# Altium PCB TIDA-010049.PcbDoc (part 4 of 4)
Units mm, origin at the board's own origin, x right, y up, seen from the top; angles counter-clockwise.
Board outline 75 x 60 mm, 4 copper layers (Top Layer, GND, Supply, Bottom Layer), stack 1.565 mm thick; 309 components, 186 nets, 995 pads, 362 vias.
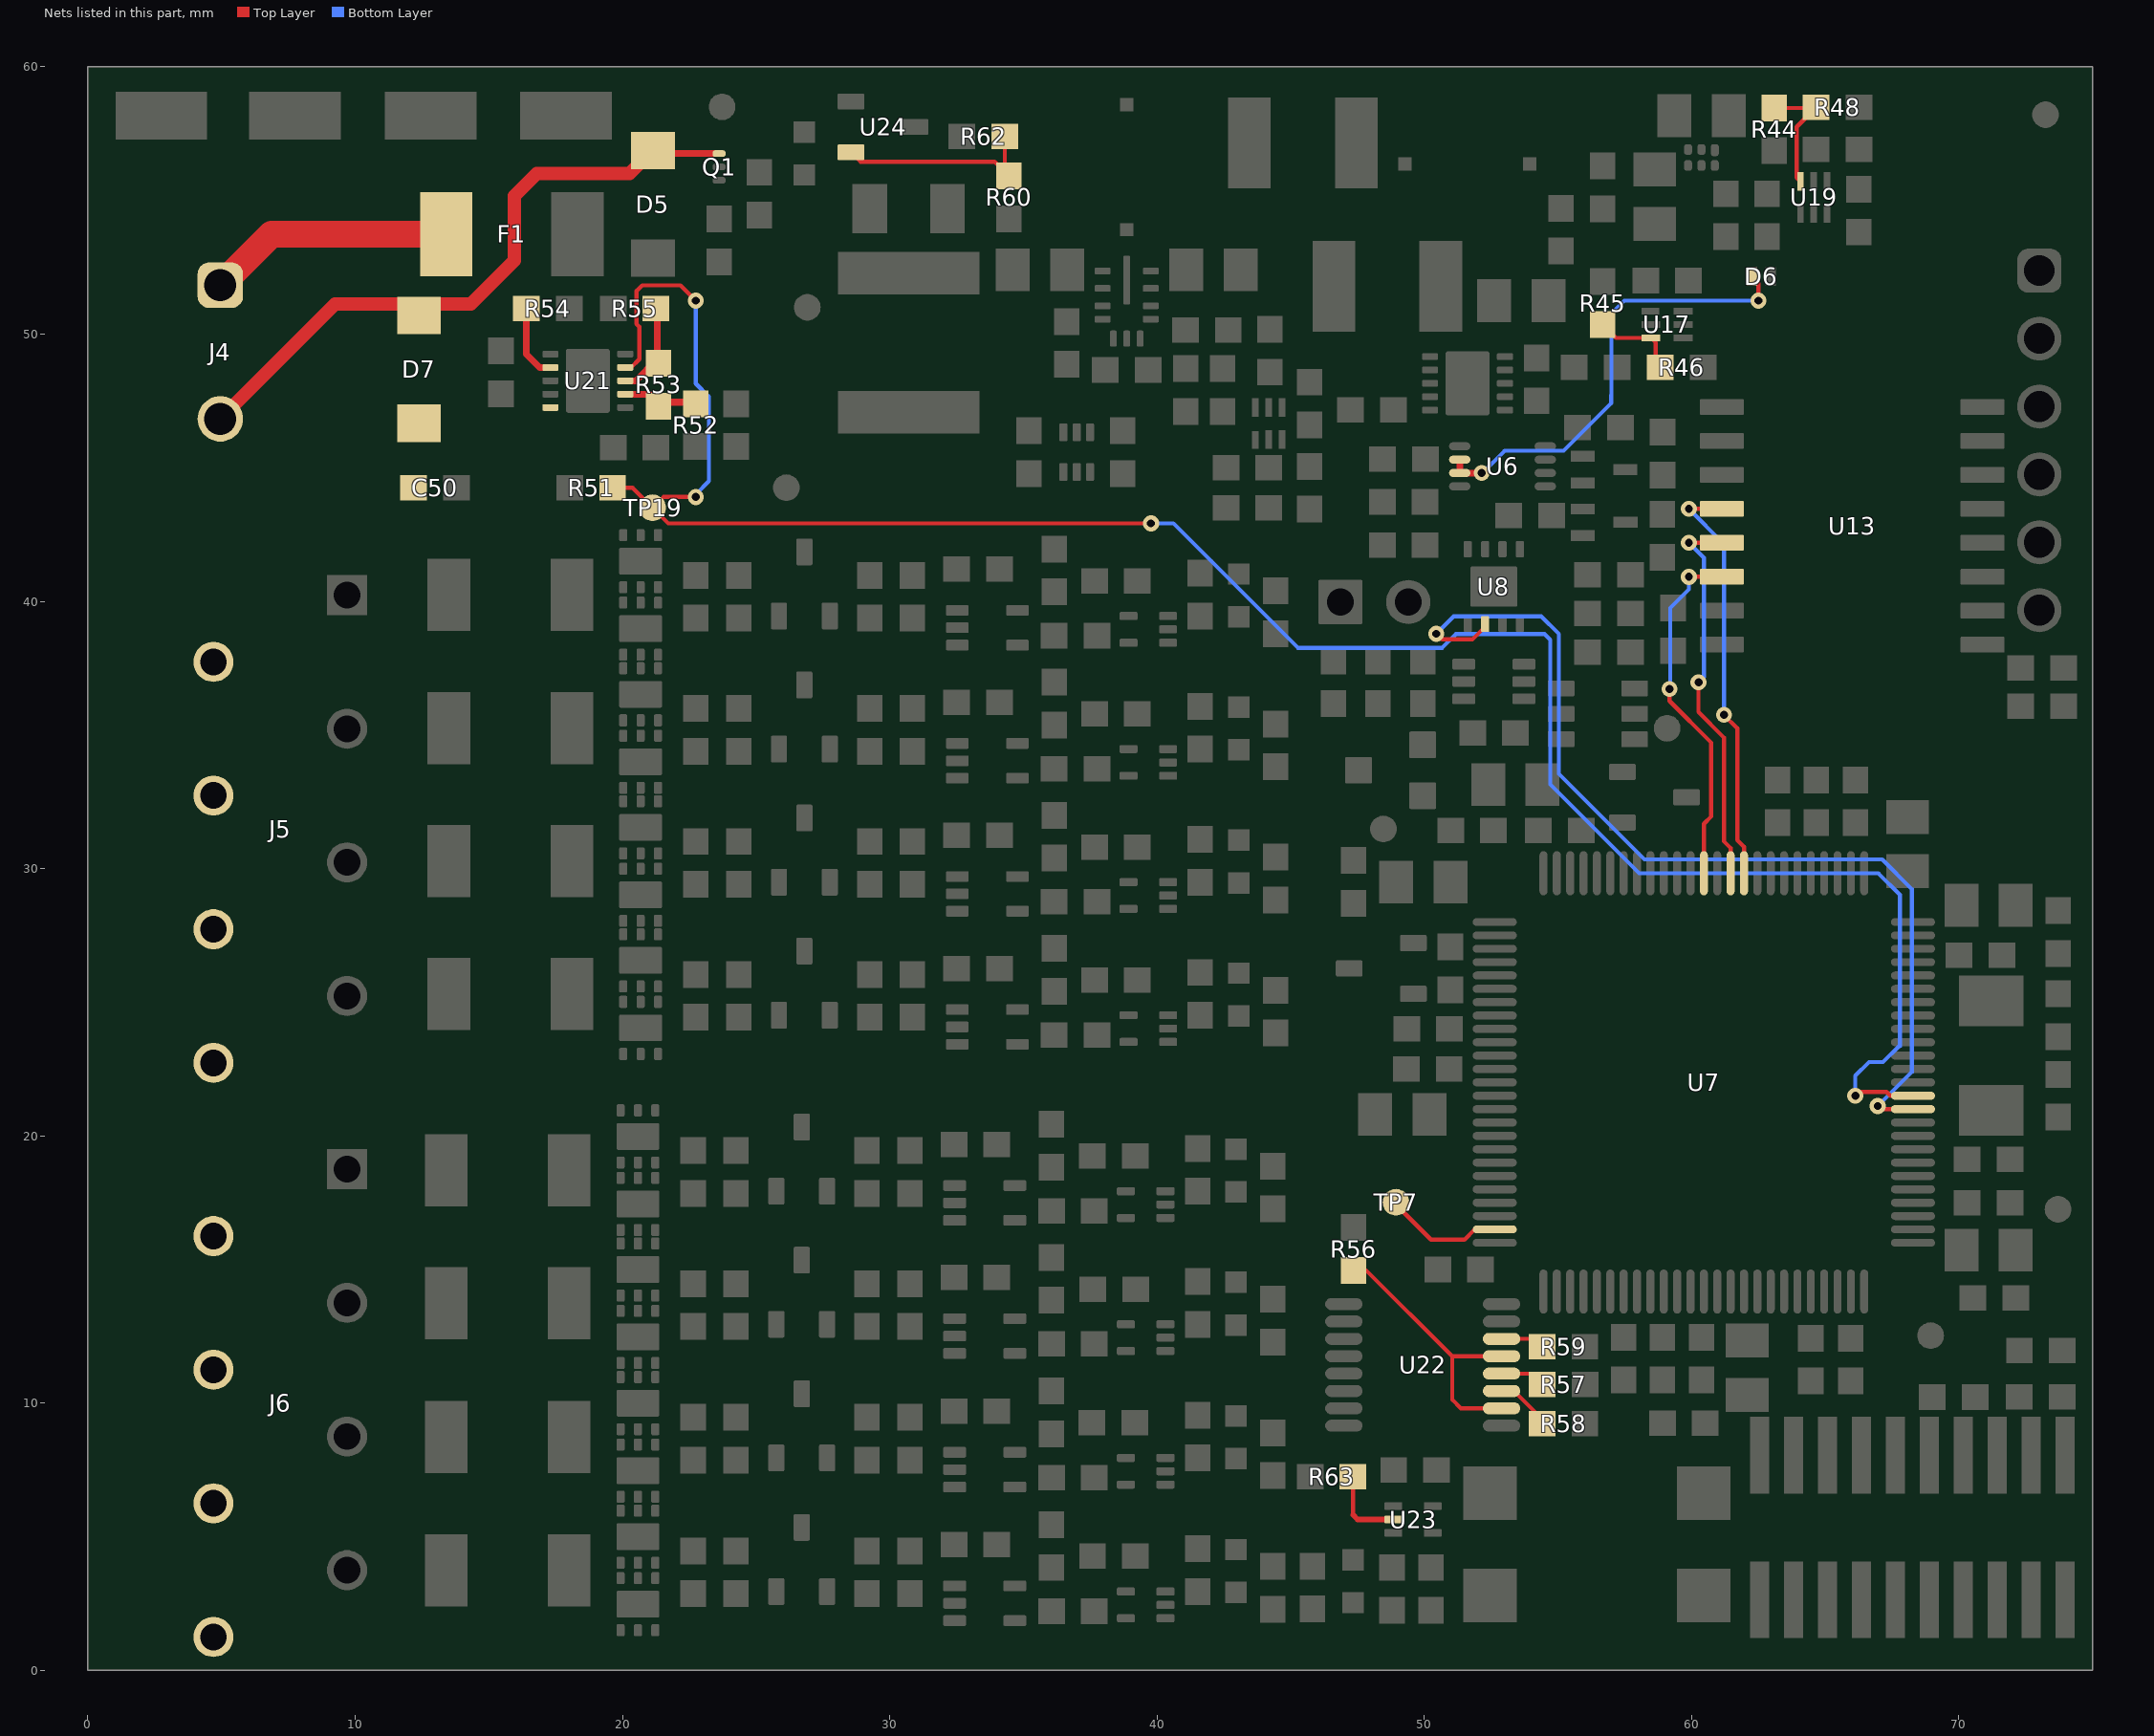
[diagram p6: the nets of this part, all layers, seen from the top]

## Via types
v1: diameter 0.6, hole 0.3, Top Layer to Bottom Layer, 318 vias
v2: diameter 0.5, hole 0.2, Top Layer to Bottom Layer, 44 vias

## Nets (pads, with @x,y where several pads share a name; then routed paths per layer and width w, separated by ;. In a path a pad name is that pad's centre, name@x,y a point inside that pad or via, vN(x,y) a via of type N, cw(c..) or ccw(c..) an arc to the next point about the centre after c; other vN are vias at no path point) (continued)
NetR44_2: R44.2 R48.1 U19.3 | length 4.7
  Top Layer w0.152: R44.2@63.082,58.458 R48.1@64.638,58.458 ; U19.3@64.073,55.713 63.929,55.857 63.929,57.749 R48.1@64.638,58.458 ; R48.1@64.658,58.477 R48.1@64.638,58.458
NetR45_1: R45.1 R46.1 U17.3 | length 3.1
  Top Layer w0.152: R45.1@56.666,50.357 57.169,49.855 U17.3@58.483,49.855 58.658,49.68 R46.1@58.658,48.864
NetR52_2: R52.2 R53.1 U21.2 | length 2.8
  Top Layer w0.254: U21.2@20.108,47.75 20.999,47.75 21.299,47.45 22.697,47.45 R52.2@22.747,47.4
NetR53_2: R53.2 R55.1 U21.3 | length 3.3
  Top Layer w0.254: U21.3@20.108,48.25 20.499,48.25 21.299,49.05 21.299,50.759 R55.1@21.258,50.8
NetR54_1: R54.1 U21.7 | length 2.7
  Top Layer w0.254: R54.1@16.408,50.8 16.408,49.25 16.908,48.75 U21.7@17.308,48.75
NetR56_2: R56.2 U22.10 U22.13 | length 10.5
  Top Layer w0.152: R56.2@47.347,14.968 47.829,14.968 51.042,11.755 ; U22.10@52.889,9.805 51.367,9.805 51.042,10.13 51.042,11.755 ; U22.13@52.889,11.755 51.042,11.755
NetR57_2: R57.2 U22.12 | length 1.7
  Top Layer w0.152: U22.12@52.889,11.105 54.053,11.105 R57.2@54.408,10.75
NetR58_2: R58.2 U22.11 | length 2.1
  Top Layer w0.152: U22.11@52.889,10.455 53.355,10.455 54.408,9.402 R58.2@54.408,9.25
NetR59_2: R59.2 U22.14 | length 1.6
  Top Layer w0.152: U22.14@52.889,12.405 54.25,12.405 R59.2@54.408,12.246
NetR60_2: R60.2 R62.1 U24.2 | length 7.6
  Top Layer w0.152: U24.2@28.55,56.8 28.903,56.447 33.924,56.447 R60.2@34.304,56.067 ; R62.1@34.304,57.397 R60.2@34.304,56.067 ; R60.2@34.458,55.913 R60.2@34.304,56.067
NetR63_2: R63.2 U23.2 | length 3
  Top Layer w0.152: 47.333,5.82 R63.2@47.333,7.25
  Top Layer w0.203: 47.333,5.82 47.506,5.647 U23.2@48.839,5.647
NetTP7_1: TP7.1 U7.74 | length 4.5
  Top Layer w0.152: TP7.1@48.942,17.514 48.942,17.423 50.25,16.115 51.505,16.115 51.89,16.5 U7.74@52.633,16.5
NetU7_35: U7.35 U13.12 | length 15.7
  Top Layer w0.152: v1(59.898,43.46) U13.12@61.133,43.46 ; v1(61.208,35.75) 61.708,35.25 61.708,31.068 61.958,30.818 U7.35@61.958,29.825
  Bottom Layer w0.152: v1(59.898,43.46) 61.208,42.15 v1(61.208,35.75)
NetU7_36: U7.36 U13.13 | length 14.4
  Top Layer w0.152: v1(59.898,42.19) U13.13@61.133,42.19 ; v1(60.258,36.971) 60.258,35.858 61.208,34.908 61.208,31.025 61.458,30.775 U7.36@61.458,29.825
  Bottom Layer w0.152: v1(59.898,42.19) 60.458,41.63 60.458,37.171 v1(60.258,36.971)
NetU7_38: U7.38 U13.14 | length 13.4
  Top Layer w0.152: v1(59.17,36.721) 59.17,36.272 60.733,34.709 60.733,31.95 60.458,31.675 U7.38@60.458,29.825 ; v1(59.898,40.915) 59.903,40.92 U13.14@61.133,40.92
  Bottom Layer w0.152: v1(59.17,36.721) 59.202,36.754 59.202,39.753 59.898,40.448 v1(59.898,40.915)
SENSSUP: C50.1 D7.2 J5.2 J5.4 J5.6 J5.8 J6.2 J6.4 J6.6 J6.8 U21.10
SENSSUP_CTRL: R51.2 TP19.1 U7.12 U21.4 | length 84.2
  Top Layer w0.152: R51.2@19.633,44.25 20.381,44.25 TP19.1@21.131,43.5 ; U21.4@20.108,48.75 20.327,48.75 20.637,49.06 20.637,50.271 20.529,50.378 20.529,51.611 20.743,51.825 22.172,51.825 v1(22.747,51.25) ; v1(22.747,43.903) 21.534,43.903 TP19.1@21.131,43.5 ; v1(39.776,42.917) 21.714,42.917 21.575,43.056 TP19.1@21.131,43.5 ; v1(66.124,21.5) 66.268,21.644 67.289,21.644 67.433,21.5 U7.12@68.283,21.5
  Bottom Layer w0.152: v1(22.747,43.903) 22.753,43.903 22.753,44.012 23.237,44.495 23.237,47.659 22.747,48.148 v1(22.747,51.25) ; v1(39.776,42.917) 40.614,42.917 45.27,38.26 50.666,38.26 51.182,38.776 54.493,38.776 54.708,38.561 54.708,33.151 58.034,29.825 66.984,29.825 67.791,29.017 67.791,23.355 67.755,23.355 67.161,22.761 66.636,22.761 66.124,22.249 v1(66.124,21.5)
STICKY_1.25V_OV: D6.2 U6.2 U6.3 | length 17.3
  Top Layer w0.152: D6.2@62.253,52.147 62.5,51.9 v1(62.5,51.25)
  Top Layer w0.254: U6.2@51.325,45.3 U6.3@51.325,44.8 v1(52.147,44.8) v1@52.175,44.8
  Bottom Layer w0.152: v1(52.147,44.8) 52.175,44.8 53.006,45.631 55.209,45.631 56.994,47.416 56.994,47.719 57,47.725 57,50.766 57.484,51.25 v1(62.5,51.25)
V_GND: D5.1 D7.1 J4.2 Q1.3@23.616,56.75 | length 24.3
  Top Layer w0.25: D5.1@21.254,56.75 Q1.3@23.616,56.75
  Top Layer w0.5: J4.2@4.958,46.825 9.253,51.12 12.208,51.12 14.328,51.12 15.958,52.75 15.958,55.163 16.795,56 20.274,56 D5.1@21.139,56.865 D5.1@21.254,56.75
V_SUPPLY: F1.2 J4.1 | length 9.2
  Top Layer w1: J4.1@4.958,51.825 6.875,53.742 F1.2@13.366,53.742
WDI: U7.11 U8.6 | length 37.6
  Top Layer w0.152: v1(50.448,38.786) 50.659,38.575 51.799,38.575 52.275,39.051 U8.6@52.275,39.15 ; v1(66.963,21.115) 67.078,21 U7.11@68.283,21
  Bottom Layer w0.152: v1(50.448,38.786) 51.101,39.439 54.374,39.439 55.033,38.78 55.033,33.543 58.236,30.339 67.134,30.339 68.235,29.237 68.235,22.388 v1(66.963,21.115)
pads on no net: FID1.1 FID2.1 FID3.1 H1.0 H2.0 H3.0 H4.0 J1.6 LBL1.0 Q1.1@23.616,55.725 Q1.2@23.616,56.25 Q1.3@23.616,56.775 U3_1.7@20.231,38.975 U3_1.7@21.131,38.975 U3_2.7@20.231,33.996 U3_2.7@21.131,33.996 U3_3.7@20.231,29.018 U3_3.7@21.131,29.018 U3_4.7@20.231,24.039 U3_4.7@21.131,24.039 U3_5.7@20.131,17.453 U3_5.7@21.031,17.453 U3_6.7@20.131,12.475 U3_6.7@21.031,12.475 U3_7.7@20.131,7.475 U3_7.7@21.031,7.475 U3_8.7@20.131,2.475 U3_8.7@21.031,2.475 U4_1.7@20.231,41.5 U4_1.7@21.131,41.5 U4_2.7@20.231,36.521 U4_2.7@21.131,36.521 U4_3.7@20.231,31.543 U4_3.7@21.131,31.543 U4_4.7@20.231,26.564 U4_4.7@21.131,26.564 U4_5.7@20.131,19.978 U4_5.7@21.031,19.978 U4_6.7@20.131,15 U4_6.7@21.031,15 U4_7.7@20.131,10 U4_7.7@21.031,10 U4_8.7@20.131,5 U4_8.7@21.031,5 U7.3 U7.4 U7.37 U7.58 U7.62 U7.63 U7.69 U7.84 U7.91 U7.92 U7.94 U7.95 U11.4 U13.7 U13.10 U15.3 U15.4 U17.4 U17.6 U22.9
copper on no net: | length 1.7
  Top Layer w0.203: v1(56.165,34.84) 57.868,34.84
  other v1: 41.516,5.654

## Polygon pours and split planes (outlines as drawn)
SENSSUP on Top Layer "TOP_LAYER_SENSSUP_P020" (solid, remove dead copper, pour order 20): 17.634,47.45 7,47.45 2.5,42.909 2.5,0 7,0 7,40.7 9.493,43.193 17.634,43.193
DGND on Top Layer "TOP_LAYER_DGND_P018" (solid, remove dead copper, pour order 18): 74.708,54.931 74.708,35.232 71.649,35.232 70.092,38.741 70.092,47.657 71.252,47.657 71.249,50.077 72.176,51.004 72.176,54.931
GND on Top Layer "TOP_LAYER_GND_P016" (solid, remove dead copper, pour order 16): 19.398,1.208 43.648,1.208 43.648,42.693 19.413,42.693 19.398,42.708
no net on Top Layer "TOP_LAYER_NONET_P012" (solid, remove dead copper, pour order 12): 19.708,1.425
NetC51_2 on Top Layer "TOP_LAYER_NETC51_2_P010" (solid, remove dead copper, pour order 10): 15.458,51.957 15.458,49.045 17.861,49.028 17.861,43.721 20.358,43.721 20.358,51.957
3.3V on Top Layer "TOP_LAYER_3.3V_P008" (solid, remove dead copper, pour order 8): 52.846,59 52.846,45.631 58.486,45.631 58.486,59
GND on Top Layer "TOP_LAYER_GND_P004" (solid, remove dead copper, pour order 4): 49.842,53.5 49.86,53.482 52.958,53.482 52.958,46.35 49.842,46.35
24V on Top Layer "TOP_LAYER_24V_P000" (solid, remove dead copper, pour order 0): 25.839,57 42.208,57 42.208,45.189 42.208,43.699 19.667,43.699 19.667,50.828
GND on GND "GND_GND_P002" (solid, remove dead copper, pour order 2): 0,60 0,-0.313 75.25,-0.313 75.007,26.201 66.458,34.75 61.297,34.75 60.504,35.544 60.504,48.796 67.999,56.195 67.999,60
3.3V on Supply "SUPPLY_3.3V_P006" (solid, remove dead copper, pour order 6): 23.237,59 23.237,46.75 34.208,46.75 34.208,1.2 74.475,1.2 74.475,11.566 74.475,31.832 64.84,31.832 61.958,34.714 61.958,49.125 67.708,54.875 67.708,58.98 58.616,58.87 58.487,59

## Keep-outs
Keep-Out Layer:
  text ".Layer_Name" at 14.656,-21.806 h1.52

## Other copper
Top Layer:
  text "TIDA-010049E2" at 0.5,55.246 h1.8
  text ".Layer_Name" at 14.656,-21.806 h1.52
Bottom Layer:
  region net MASK_COLD_RST: 68.75,14.142
  text ".Layer_Name" at 14.656,-21.806 h1.52

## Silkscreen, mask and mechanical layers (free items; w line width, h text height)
Top Overlay:
  lines w0.254: 11.908,6.25 11.929,6.229 ; 11.908,11.25 11.908,11.25
  text ".Layer_Name" at 14.656,-21.806 h1.52
Bottom Overlay:
  text "TIDA-010049E2" at 8.25,41.285 h3 r90
  text ".Layer_Name" at 14.656,-21.806 h1.52
Top Paste:
  text ".Layer_Name" at 14.656,-21.806 h1.52
Bottom Paste:
  text ".Layer_Name" at 14.656,-21.806 h1.52
Top Solder:
  text ".Layer_Name" at 14.656,-21.806 h1.52
  text ".Layer_Name" at 14.656,-21.806 h1.52
Bottom Solder:
  text ".Layer_Name" at 14.656,-21.806 h1.52
Drill Guide:
  text ".Layer_Name" at 14.656,-21.806 h1.52
M1 Board Outline:
  lines w0.254: 0,0 75,0 75,59.949 0.048,60 0,0 ; 125.73,21.907 125.73,21.908
  text ".Layer_Name" at 14.656,-21.806 h1.52
M2 Board Dimensions:
  rectangle: 0,-6.985 3.175,-3.81
  rectangle: 3.175,-10.16 12.7,-6.985
  lines w0.178: 0,-6.985 25.4,-6.985 ; 3.175,-10.16 3.175,-3.81 ; 6.35,-10.16 6.35,-3.81 ; 12.7,-10.16 12.7,-3.81 ; 19.05,-10.16 19.05,-3.81 ; 0,-10.16 25.4,-10.16 25.4,-3.81 0,-3.81 0,-10.16
  text ".Layer_Name" at 14.656,-21.806 h1.52
M3 3D STEP Top:
  text ".Layer_Name" at 14.656,-21.806 h1.52
M4 3D STEP Bottom:
  text ".Layer_Name" at 14.656,-21.806 h1.52
M5 Assembly Top:
  lines w0.254: -7.417,-23.626 160.223,-23.626 ; -7.417,-18.462 160.274,-18.462 ; -7.417,-13.297 -7.417,-28.791 94.31,-28.791 160.274,-28.791 160.274,-13.297 -7.404,-13.297 -7.404,-28.791 32.614,-28.791 ; 55.194,-28.791 55.194,-13.297 ; 87.376,-18.462 87.376,-13.297 ; 108.712,-18.462 108.712,-13.297 ; 124.511,-28.956 124.511,-23.804
  text "COMPONENTS MARKED 'DNP' SHOULD NOT BE POPULATED." at 29.299,-8.09 h1.52
  text "ASSEMBLY VARIANT:" at 29.286,-11.024 h1.52
  text ".VariantName" at 55.601,-11.024 h1.52
  text "PCB VIEWED FROM TOP SIDE" at -5.804,-16.654 h1.52
  text "BOARD #:" at 57.099,-16.654 h1.52
  text ".PRJ_Number" at 70.955,-16.654 h1.52
  text "REV:" at 92.405,-16.654 h1.52
  text ".PCB_Rev" at 99.809,-16.654 h1.52
  text "SVN REV:" at 113.69,-16.654 h1.52
  text ".VersionControl_RevNumber" at 126.543,-16.654 h1.52
  text "TID #:" at 57.099,-21.819 h1.52
  text ".TID" at 70.955,-21.819 h1.52
  text "PLOT NAME =" at -5.804,-27.034 h1.52
  text ".plot_File_Name" at 14.656,-27.034 h1.52
  text "GENERATED    :" at 57.15,-27.034 h1.52
  text ".Print_Date" at 79.235,-27.034 h1.52
  text ".Print_Time" at 97.752,-27.034 h1.52
  text "TEXAS INSTRUMENTS" at 129.87,-27.034 h1.52
M6 Assembly Bottom:
  lines w0.254: -7.429,-18.474 160.261,-18.474 ; -7.379,-23.639 160.261,-23.639 ; 28.334,-28.969 28.334,-23.817 ; 44.133,-18.474 44.133,-13.31 ; 65.468,-18.474 65.468,-13.31 ; 97.65,-28.804 97.65,-13.31 ; 120.231,-28.804 160.249,-28.804 160.249,-13.31 -7.429,-13.31 -7.429,-28.804 58.534,-28.804 160.261,-28.804 160.261,-13.31
  text "COMPONENTS MARKED 'DNP' SHOULD NOT BE POPULATED." at 154.991,-8.077 h1.52
  text ".VariantName" at 128.473,-11.024 h1.52
  text "ASSEMBLY VARIANT:" at 154.864,-11.024 h1.52
  text ".VersionControl_RevNumber" at 26.302,-16.667 h1.52
  text "SVN REV:" at 39.154,-16.667 h1.52
  text ".PCB_Rev" at 53.035,-16.667 h1.52
  text "REV:" at 60.439,-16.667 h1.52
  text ".PRJ_Number" at 81.89,-16.667 h1.52
  text "BOARD #:" at 95.745,-16.667 h1.52
  text "PCB VIEWED FROM BOTTOM SIDE" at 158.648,-16.667 h1.52
  text ".TID" at 81.89,-21.831 h1.52
  text "TID #:" at 95.745,-21.831 h1.52
  text "TEXAS INSTRUMENTS" at 22.974,-27.047 h1.52
  text ".Print_Time" at 55.093,-27.047 h1.52
  text ".Print_Date" at 73.609,-27.047 h1.52
  text "GENERATED    :" at 95.694,-27.047 h1.52
  text ".plot_File_Name" at 138.189,-27.047 h1.52
  text "PLOT NAME =" at 158.648,-27.047 h1.52
M9 Title Sheet:
  drawing of 57 lines, arcs and shapes, not listed
  text "2" at 85.916,204.197 h1.78
  text "3" at 149.145,204.197 h1.78
  text "1" at 18.792,204.127 h1.78
  text "4" at 209.08,204.127 h1.78
  text "5" at 272.555,204.127 h1.78
  text "6" at 336.182,204.127 h1.78
  text "A" at -10.579,175.095 h1.78
  text "A" at 365.341,175.095 h1.78
  text "B" at -10.579,114.643 h1.78
  text "B" at 365.341,114.643 h1.78
  text "C" at -10.579,54.318 h1.78
  text "C" at 365.341,54.318 h1.78
  text "PROJECT TITLE:" at 288.125,7.048 h1.14
  text ".PRJ_Title" at 289.395,3.662 h1.78
  text "DESIGNED FOR:" at 288.125,-0.597 h1.14
  text ".PRJ_Customer" at 289.395,-4.153 h1.78
  text "D" at -10.579,-5.88 h1.78
  text "D" at 365.341,-5.88 h1.78
  text "FILE NAME:" at 288.125,-8.217 h1.14
  text ".PCB_File_Name_No_Path" at 289.395,-11.265 h1.78
  text "Texas Instruments (TI) and/or its licensors do not warrant the accuracy or completeness of this specification" at 161.9,-15.376 h1.14
  text "ENGINEER:" at 288.125,-15.583 h1.14
  text "LAYOUT BY:" at 326.352,-15.583 h1.14
  text "or any information contained therein. TI and/or its licensors do not warrant that this design will meet" at 160.757,-18.237 h1.14
  text ".PRJ_Engineer" at 289.395,-19.52 h1.78
  text ".PCB_Layout" at 327.635,-19.52 h1.78
  text "the specifications, will be suitable for your application or fit for any particular purpose, or will operate in" at 160.757,-21.099 h1.14
  text ".Layer_Name" at 14.656,-21.806 h1.52
  text "ALTIUM DESIGNER VERSION:" at 326.352,-23.457 h1.14
  text "an implementation. TI and/or its licensors do not warrant that the design is production worthy. You should" at 160.757,-23.961 h1.14
  text "completely validate and test your design implementation to confirm the system functionality for your application." at 161.9,-26.822 h1.14
  text ".print_Scale" at 289.395,-26.843 h1.78
  text ".Application_BuildNumber" at 327.635,-26.843 h1.78
  text "1" at 18.792,-32.093 h1.78
  text "2" at 82.182,-32.093 h1.78
  text "3" at 145.411,-32.093 h1.78
  text "4" at 209.08,-32.093 h1.78
  text "5" at 272.555,-32.093 h1.78
  text "6" at 336.182,-32.093 h1.78
M10 Fab Notes:
  drawing of 189 lines, arcs and shapes, not listed
  text "DESIGN INFORMATION" at 314.503,161.447 h1.52
  text "MIN. TRACK WIDTH:" at 298.131,158.091 h1.52
  text "8" at 325.976,158.091 h1.52
  text "MIL" at 329.907,158.091 h1.52
  text "MIN. CLEARANCE:" at 298.131,154.938 h1.52
  text "0.2" at 324.452,154.938 h1.52
  text "mm" at 329.907,154.938 h1.52
  text "MIN. VIA PAD SIZE:" at 298.131,151.785 h1.52
  text "24" at 325.214,151.785 h1.52
  text "MIL" at 329.907,151.785 h1.52
  text "0.05mm (2MIL)" at 315.784,148.486 h1.52
  text "MINIMUM ANNULAR RING" at 289.769,148.277 h1.52
  text "EXTERNAL" at 333.768,148.277 h1.52
  text "PER" at 294.849,145.48 h1.52
  text "IPC-D-275 CLASS 2 LEVEL C" at 300.437,145.48 h1.52
  text "MIL, HOLES" at 338.238,142.928 h1.52
  text "+/-" at 328.27,142.709 h1.52
  text "+/-" at 349.961,142.709 h1.52
  text "REGISTRATION TOLERANCES:" at 289.769,142.682 h1.52
  text "METAL" at 320.243,142.682 h1.52
  text "5" at 334.879,142.683 h1.52
  text "3" at 356.037,142.683 h1.52
  text "MIL" at 358.99,142.682 h1.52
  text "HOLE SIZE TOLERANCE (UNLESS OTHERWISE SPECIFIED):" at 289.769,140.185 h1.52
  text "+/-" at 349.961,140.112 h1.52
  text "3" at 356.037,140.085 h1.52
  text "MIL" at 358.99,140.085 h1.52
  text "MATERIAL:" at 287.87,136.589 h1.52
  text "FR-4 High Tg" at 312.926,133.324 h1.52
  text "X" at 309.257,133.122 h1.52
  text "FR-408" at 298.563,133.007 h1.52
  text "OTHER" at 336.358,133.007 h1.52
  text "62 MIL (1.6mm) +/-10%" at 306.694,129.374 h1.52
  text "X" at 303.643,129.312 h1.52
  text "THICKNESS:" at 289.769,129.165 h1.52
  text "OTHER" at 339.33,129.165 h1.52
  text "TOLERANCE:" at 289.769,125.652 h1.52
  text "X" at 311.314,125.652 h1.52
  text "ANSI IPC-6012 TYPE 3 CLASS 2" at 315.836,125.652 h1.52
  text "OTHER +/-" at 315.835,121.989 h1.52
  text "BOW & TWIST:" at 289.769,118.302 h1.52
  text "X" at 311.314,118.302 h1.52
  text "ANSI IPC-6012 TYPE 3 CLASS 2" at 315.836,118.302 h1.52
  text "OTHER +/-" at 315.835,114.576 h1.52
  text "DRILLING:" at 287.87,111.258 h1.52
  text "NC_DRILL FILES" at 332.599,108.586 h1.52
  text "REFERENCE:" at 289.769,108.486 h1.52
  text "X" at 306.463,108.484 h1.52
  text "AS SHOWN" at 310.984,108.486 h1.52
  text "X" at 329.348,108.486 h1.52
  text "OTHER" at 340.168,104.873 h1.52
  text "PTH COPPER THICKNESS:" at 289.761,104.783 h1.52
  text "X" at 318.697,104.783 h1.52
  text "20-30 um" at 321.948,104.783 h1.52
  text "BOARD FINISH:" at 287.87,101.034 h1.52
  text "SILKSCREEN:" at 291.812,98.237 h1.52
  text "X" at 316.14,98.237 h1.52
  text "TOP" at 319.112,98.237 h1.52
  text "X" at 329.094,98.237 h1.52
  text "BOTTOM" at 332.091,98.237 h1.52
  text "SILKSCREEN COLOR:" at 291.812,94.295 h1.52
  text "X" at 316.115,94.295 h1.52
  text "WHITE" at 319.112,94.295 h1.52
  text "OTHER" at 332.091,94.295 h1.52
  text "X" at 319.442,90.652 h1.52
  text "GREEN" at 322.439,90.652 h1.52
  text "OTHER" at 338.136,90.652 h1.52
  text "SOLDER RESIST COLOR:" at 291.812,90.477 h1.52
  text "X" at 319.442,86.734 h1.52
  text "MATTE" at 322.439,86.734 h1.52
  text "SEMI-GLOSS" at 338.125,86.717 h1.52
  text "IMMERSION GOLD (ENIG)" at 314.819,82.345 h1.52
  text "ENEPIG" at 348.793,82.162 h1.52
  text "SURFACE FINISH:" at 287.87,82.136 h1.52
  text "X" at 310.298,82.136 h1.52
  text "IMM. TIN/SILVER OR EQUIV" at 296.24,78.649 h1.52
  text "OTHER" at 332.599,78.549 h1.52
  text "ARRAY/PANEL:" at 287.87,74.602 h1.52
  text "CUT AND TRIM PER M1 BOARD OUTLINE" at 314.819,74.393 h1.52
  text "N.C. ROUTE" at 314.819,70.94 h1.52
  text "X" at 332.295,70.94 h1.52
  text "V. SCORE" at 336.816,70.94 h1.52
  text "CERTIFICATION:" at 287.87,67.66 h1.52
  text "MATERIALS AND WORKMANSHIP FOR ALL PCBS" at 306.285,67.66 h1.52
  text "TO MEET OR EXCEED THE REQUIREMENTS OF:" at 306.285,65.271 h1.52
  text "X" at 297.078,62.003 h1.52
  text "ANSI IPC-A-600F CLASS ->" at 300.329,62.003 h1.52
  text "X" at 342.188,62.003 h1.52
  text "2" at 344.982,62.003 h1.52
  text "1" at 336.981,61.965 h1.52
  text "3" at 353.973,61.965 h1.52
  text "X" at 317.702,58.252 h1.52
  text "RoHS" at 320.953,58.252 h1.52
  text "OTHER" at 337.321,58.252 h1.52
  text "PER ORDER" at 347.407,58.252 h1.52
  text "ALL BOARDS MUST MEET OR EXCEED UL94-V0 REQUIREMENTS." at 288.569,54.345 h1.52
  text "PCB MUST BEAR THE UL94V-0 UL REGISTERED MATERIAL ID NUMBER" at 288.569,51.397 h1.52
  text "ADDITIONAL REQUIREMENTS:" at 287.87,47.094 h1.52
  text "MICROSECTION:" at 289.769,44.373 h1.52
  text "YES" at 312.775,44.373 h1.52
  text "REQUIRED" at 334.657,40.707 h1.52
  text "BARE BOARD ELEC. TEST:" at 289.769,40.634 h1.52
  text "NONE" at 322.935,40.634 h1.52
  text "X" at 331.66,40.634 h1.52
  text "PER ORDER" at 349.693,40.634 h1.52
  text "XX MIL VIAS REQUIRE NON-CONDUCTIVE FILL AND PLANARIZE" at 294.04,35.428 h1.5
  text "XX MIL VIAS REQUIRE CONDUCTIVE FILL AND PLANARIZE" at 294.243,32.787 h1.52
  text "OUTER XX MIL TRACES REQUIRE 50 OHM SINGLE-ENDED IMPEDANCE" at 294.218,28.637 h1.47
  text "LAYER 2 & 3 (INNER LAYERS) XX MIL WIDE, XX MIL SPACE / TRACES REQUIRE 100 OHM DIFFERENTIAL IMPEDANCE" at 294.015,22.65 h1.52
  text ".Layer_Name" at 14.656,-21.806 h1.52
M11 Gerber Information:
  lines w0.254: -7.417,-23.626 160.223,-23.626 ; -7.417,-18.462 160.274,-18.462 ; -7.417,-13.297 -7.417,-28.791 94.31,-28.791 160.274,-28.791 160.274,-13.297 -7.404,-13.297 -7.404,-28.791 32.614,-28.791 ; 55.194,-28.791 55.194,-13.297 ; 87.376,-18.462 87.376,-13.297 ; 108.712,-18.462 108.712,-13.297 ; 124.511,-28.956 124.511,-23.804
  text "ALL ARTWORK VIEWED FROM TOP SIDE" at -5.804,-16.654 h1.52
  text "BOARD #:" at 57.099,-16.654 h1.52
  text ".PRJ_Number" at 70.955,-16.654 h1.52
  text "REV:" at 92.405,-16.654 h1.52
  text ".PCB_Rev" at 99.809,-16.654 h1.52
  text "SVN REV:" at 113.69,-16.654 h1.52
  text ".VersionControl_RevNumber" at 126.543,-16.654 h1.52
  text "LAYER NAME =" at -5.804,-21.806 h1.52
  text "TID #:" at 57.099,-21.819 h1.52
  text ".TID" at 70.955,-21.819 h1.52
  text "PLOT NAME =" at -5.804,-27.034 h1.52
  text ".plot_File_Name" at 14.656,-27.034 h1.52
  text "GENERATED    :" at 57.15,-27.034 h1.52
  text ".Print_Date" at 79.235,-27.034 h1.52
  text ".Print_Time" at 97.752,-27.034 h1.52
  text "TEXAS INSTRUMENTS" at 129.87,-27.034 h1.52
M12 Stackup:
  drawing of 295 lines, arcs and shapes, not listed
  text "Layer" at 248.865,182.308 h1.52
  text "Name" at 259.277,182.308 h1.52
  text "Material" at 282.892,182.308 h1.52
  text "Thickness" at 304.731,182.308 h1.52
  text "Constant" at 321.236,182.308 h1.52
  text "Board Layer Stack" at 335.711,182.308 h1.52
  text "1" at 248.865,179.26 h1.52
  text "Top Overlay" at 259.277,179.26 h1.52
  text "2" at 248.865,176.213 h1.52
  text "Top Solder" at 259.277,176.213 h1.52
  text "Solder Resist" at 282.892,176.213 h1.52
  text "0.40mil" at 304.731,176.213 h1.52
  text "3.5" at 321.236,176.213 h1.52
  text "3" at 248.865,173.165 h1.52
  text "Top Layer" at 259.277,173.165 h1.52
  text "Copper" at 282.892,173.165 h1.52
  text "1.40mil" at 304.731,173.165 h1.52
  text "4" at 248.865,170.117 h1.52
  text "Dielectric 1" at 259.277,170.117 h1.52
  text "FR-4" at 282.892,170.117 h1.52
  text "8.00mil" at 304.731,170.117 h1.52
  text "4.2" at 321.236,170.117 h1.52
  text "5" at 248.865,167.069 h1.52
  text "GND" at 259.277,167.069 h1.52
  text "Copper" at 282.892,167.069 h1.52
  text "1.40mil" at 304.731,167.069 h1.52
  text "6" at 248.865,164.02 h1.52
  text "Dielectric 2" at 259.277,164.02 h1.52
  text "FR-4" at 282.892,164.02 h1.52
  text "40.00mil" at 304.731,164.02 h1.52
  text "4.2" at 321.236,164.02 h1.52
  text "7" at 248.865,160.972 h1.52
  text "Supply" at 259.277,160.972 h1.52
  text "Copper" at 282.892,160.972 h1.52
  text "1.40mil" at 304.731,160.972 h1.52
  text "8" at 248.865,157.924 h1.52
  text "Dielectric 3" at 259.277,157.924 h1.52
  text "FR-4" at 282.892,157.924 h1.52
  text "8.00mil" at 304.731,157.924 h1.52
  text "4.2" at 321.236,157.924 h1.52
  text "9" at 248.865,154.876 h1.52
  text "Bottom Layer" at 259.277,154.876 h1.52
  text "Copper" at 282.892,154.876 h1.52
  text "1.40mil" at 304.731,154.876 h1.52
  text "10" at 248.865,151.828 h1.52
  text "Bottom Solder" at 259.277,151.828 h1.52
  text "Solder Resist" at 282.892,151.828 h1.52
  text "0.40mil" at 304.731,151.828 h1.52
  text "3.5" at 321.236,151.828 h1.52
  text "11" at 248.865,148.78 h1.52
  text "Bottom Overlay" at 259.277,148.78 h1.52
  text ".Layer_Name" at 14.656,-21.806 h1.52
M13 Component Bodies Top:
  text ".Layer_Name" at 14.656,-21.806 h1.52
M14 Component Bodies Bottom:
  text ".Layer_Name" at 14.656,-21.806 h1.52
M15 Courtyards Top:
  text ".Layer_Name" at 14.656,-21.806 h1.52
M16 Courtyards Bottom:
  text ".Layer_Name" at 14.656,-21.806 h1.52
Drill Drawing:
  circle w0.254: c136.238,74.752 r0.702
  lines w0.254: 135.537,70.893 136.238,71.244 136.94,70.893 136.589,71.595 136.94,72.296 136.238,71.945 135.537,72.296 135.888,71.595 135.537,70.893 ; 135.537,77.559 135.888,77.559 135.888,77.208 136.589,77.208 136.589,77.559 136.94,77.559 136.94,78.261 136.589,78.261 136.589,78.612 135.888,78.612 135.888,78.261 135.537,78.261 135.537,77.559 ; 135.537,80.717 135.888,80.717 136.238,80.366 136.589,80.717 136.94,80.717 136.589,81.068 136.94,81.419 136.589,81.419 136.238,81.769 135.888,81.419 135.537,81.419 135.888,81.068 135.537,80.717 ; 135.537,83.524 136.94,83.524 136.94,84.927 135.537,84.927 135.537,83.524 ; 135.537,88.085 136.94,88.085 136.238,86.681 135.537,88.085
  lines w0.305: 134.264,69.946 216.344,69.946 ; 134.264,88.892 216.344,88.892 ; 142.846,66.788 142.846,92.05 ; 151.279,66.788 151.279,92.05 ; 167.448,66.788 167.448,92.05 ; 174.03,66.788 174.03,92.05 ; 183.559,66.788 183.559,92.05 ; 201.957,66.788 201.957,92.05 ; 134.264,66.788 216.344,66.788 216.344,92.05 134.264,92.05 134.264,66.788
  text "Symbol" at 136.159,89.839 h1.83
  text "Quantity" at 143.793,89.839 h1.83
  text "Finished Hole Size" at 152.226,89.839 h1.83
  text "Plated" at 168.395,89.839 h1.83
  text "Hole Type" at 174.977,89.839 h1.83
  text "Drill Layer Pair" at 184.506,89.839 h1.83
  text "Hole Tolerance" at 202.904,89.839 h1.83
  text "44" at 143.793,86.681 h1.52
  text "7.87mil (0.200mm)" at 152.226,86.681 h1.52
  text "PTH" at 168.395,86.681 h1.52
  text "Round" at 174.977,86.681 h1.52
  text "Top Layer - Bottom Layer" at 184.506,86.681 h1.52
  text "318" at 143.793,83.524 h1.52
  text "11.81mil (0.300mm)" at 152.226,83.524 h1.52
  text "PTH" at 168.395,83.524 h1.52
  text "Round" at 174.977,83.524 h1.52
  text "Top Layer - Bottom Layer" at 184.506,83.524 h1.52
  text "16" at 143.793,80.366 h1.52
  text "39.37mil (1.000mm)" at 152.226,80.366 h1.52
  text "PTH" at 168.395,80.366 h1.52
  text "Round" at 174.977,80.366 h1.52
  text "Top Layer - Bottom Layer" at 184.506,80.366 h1.52
  text "2" at 143.793,77.208 h1.52
  text "40.00mil (1.016mm)" at 152.226,77.208 h1.52
  text "PTH" at 168.395,77.208 h1.52
  text "Round" at 174.977,77.208 h1.52
  text "Top Layer - Bottom Layer" at 184.506,77.208 h1.52
  text "6" at 143.793,74.051 h1.52
  text "45.28mil (1.150mm)" at 152.226,74.051 h1.52
  text "PTH" at 168.395,74.051 h1.52
  text "Round" at 174.977,74.051 h1.52
  text "Top Layer - Bottom Layer" at 184.506,74.051 h1.52
  text "2" at 143.793,70.893 h1.52
  text "47.24mil (1.200mm)" at 152.226,70.893 h1.52
  text "PTH" at 168.395,70.893 h1.52
  text "Round" at 174.977,70.893 h1.52
  text "Top Layer - Bottom Layer" at 184.506,70.893 h1.52
  text "388 Total" at 143.793,67.735 h1.52
  text ".Layer_Name" at 14.656,-21.806 h1.52
Mechanical 17:
  text ".Layer_Name" at 14.656,-21.806 h1.52
Mechanical 18:
  text ".Layer_Name" at 14.656,-21.806 h1.52
Mechanical 19:
  text ".Layer_Name" at 14.656,-21.806 h1.52

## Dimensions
0,-10.16 to 25.4,-10.16 on M2 Board Dimensions
0,0 to 0,60 on M2 Board Dimensions
0,0 to 75,0 on M2 Board Dimensions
